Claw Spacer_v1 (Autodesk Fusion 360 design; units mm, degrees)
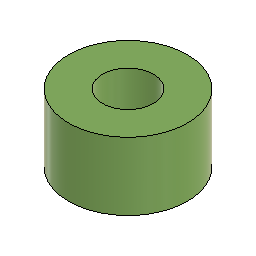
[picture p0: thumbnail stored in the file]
sketch "Sketch1" plane through (0, 0, 0) normal (0, 0, 1) x axis (1, 0, 0)
  circle C1 centre (0, 0) radius 1.5
  circle C2 centre (0, 0) radius 3.5
  point P1 (0, 0)
  point P2 (0, 0)
  coincident P1 P2
  concentric C1 C2
  dimension "d1" diameter C1 = 3
  dimension "d2" diameter C2 = 7
extrude "Extrude1" new body sketch "Sketch1" along normal blind 4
